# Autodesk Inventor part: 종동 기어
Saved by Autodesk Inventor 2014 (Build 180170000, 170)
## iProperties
Created: 2026-04
Part Number: 종동 기어
Material: 일반
Document SubType Name: Modeling
Designer: dg
Density: 1 g/cm^3
Appearance: 기본값
Author: dg
Author: jhkim
Creation Date: 2026-03-27
Sending System: Autodesk Inventor 2026
Preprocessor: ST-DEVELOPER v20.1
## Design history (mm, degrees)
node "종동 기어1"
node "솔리드1"
node "기준1"
